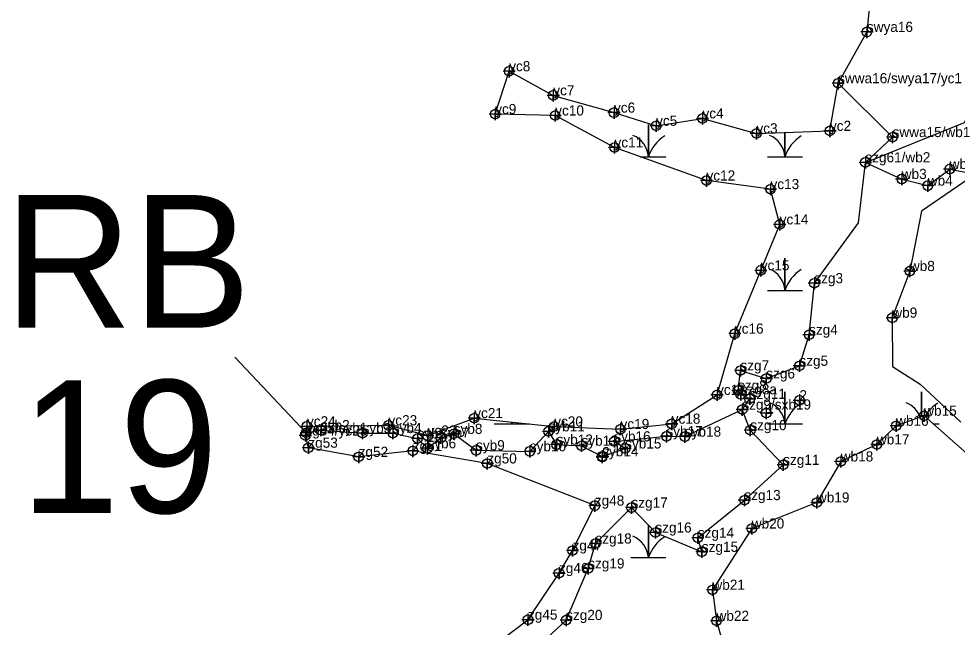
# Model space of a CAD drawing. Extents: x 2071991 to 2268989, y 436479 to 469629.
# Drawn here: x 2217530 to 2217991.7, y 438642 to 438941.5 of the extents above; entities that cross this region are included whole.
import ezdxf

# ---------------------------------------------------------------- set-up
doc = ezdxf.new("R2010")
doc.units = 0
for name, color, linetype in [('Default', 7, 'Continuous'), ('Exist Environmental Wetland Boundary', 7, 'Continuous'), ('Exist Environmental Wetland Boundary Cogo Comment', 7, 'Continuous'), ('Exist Environmental Wetland Boundary Cogo Point CELL', 7, 'Continuous'), ('Exist Hydro Jurisdictional Stream or Body of Water NEU Mitigable', 7, 'Continuous'), ('Exist Hydro Jurisdictional Stream or Body of Water NEU Mitigable Cogo Comment', 7, 'Continuous'), ('Exist Hydro Jurisdictional Stream or Body of Water NEU Mitigable Cogo Point CELL', 7, 'Continuous'), ('Exist Hydro Jurisdictional Stream or Body of Water NEU NonMitigable', 7, 'Continuous'), ('Exist Hydro Jurisdictional Stream or Body of Water NEU NonMitigable Cogo Comment', 7, 'Continuous'), ('Exist Hydro Jurisdictional Stream or Body of Water NEU NonMitigable Cogo Point CELL', 7, 'Continuous'), ('Exist Hydro Swamp or Marsh', 7, 'Continuous')]:
    doc.layers.add(name, color=color, linetype=linetype)

msp = doc.modelspace()

# ---------------------------------------------------------------- linework, layer by layer
at = {"layer": 'Default'}
msp.add_line((2217636.33, 438774.91), (2217671.41, 438737.63), dxfattribs=at)
at = {"layer": 'Exist Environmental Wetland Boundary'}
for points in [[(2217760.94, 438630.93), (2217780.52, 438645.68), (2217795.78, 438668.61), (2217802.43, 438679.75), (2217813.4, 438701.83), (2217760.51, 438722.59), (2217723.84, 438728.75), (2217697.22, 438725.8), (2217672.46, 438730.32), (2217671, 438736.35), (2217671.78, 438740.85), (2217711.9, 438741.36), (2217731.17, 438736.28), (2217754.08, 438744.89), (2217793.42, 438740.78), (2217826.06, 438739.52), (2217851.21, 438742.14), (2217873.53, 438756.36), (2217882.3, 438786.48), (2217895.04, 438817.63), (2217904.35, 438840.25), (2217899.83, 438857.62), (2217868.34, 438861.82), (2217823.08, 438878.14), (2217793.91, 438893.84), (2217764.38, 438894.56), (2217771.26, 438915.63), (2217792.96, 438903.78), (2217822.84, 438895.26), (2217843.55, 438888.8), (2217866.37, 438892.43), (2217892.9, 438885.05), (2217929.08, 438886.27), (2217933.09, 438909.73)], [(2217959.87, 438883.23), (2217946.5, 438870.8), (2217964.4, 438862.6), (2217977.21, 438859.33), (2217988, 438867.51), (2218000.66, 438865.02), (2217974.07, 438846.77), (2217968.39, 438817.3), (2217959.76, 438794.33), (2217959.88, 438770.28), (2217973.44, 438761.55), (2217993.4, 438742.94)], [(2217999.14, 438725.02), (2217975.44, 438746.08), (2217961.62, 438741.12), (2217952.17, 438731.95), (2217934.39, 438723.56), (2217922.67, 438703.38), (2217890.61, 438690.57), (2217871.26, 438660.41), (2217873.28, 438645.11), (2217881.02, 438617.93)]]:
    msp.add_lwpolyline(points, dxfattribs=at)
at = {"layer": 'Exist Environmental Wetland Boundary Cogo Point CELL'}
for points in [[(2217771.26, 438918.63), (2217771.26, 438912.63), (2217771.26, 438915.63), (2217774.26, 438915.63), (2217768.26, 438915.63)], [(2217792.96, 438906.78), (2217792.96, 438900.78), (2217792.96, 438903.78), (2217795.96, 438903.78), (2217789.96, 438903.78)], [(2217822.84, 438898.26), (2217822.84, 438892.26), (2217822.84, 438895.26), (2217825.84, 438895.26), (2217819.84, 438895.26)], [(2217764.38, 438897.56), (2217764.38, 438891.56), (2217764.38, 438894.56), (2217767.38, 438894.56), (2217761.38, 438894.56)], [(2217793.91, 438896.84), (2217793.91, 438890.84), (2217793.91, 438893.84), (2217796.91, 438893.84), (2217790.91, 438893.84)], [(2217866.37, 438895.43), (2217866.37, 438889.43), (2217866.37, 438892.43), (2217869.37, 438892.43), (2217863.37, 438892.43)], [(2217843.55, 438891.8), (2217843.55, 438885.8), (2217843.55, 438888.8), (2217846.55, 438888.8), (2217840.55, 438888.8)], [(2217929.08, 438889.27), (2217929.08, 438883.27), (2217929.08, 438886.27), (2217932.08, 438886.27), (2217926.08, 438886.27)], [(2217892.9, 438888.05), (2217892.9, 438882.05), (2217892.9, 438885.05), (2217895.9, 438885.05), (2217889.9, 438885.05)], [(2217823.08, 438881.14), (2217823.08, 438875.14), (2217823.08, 438878.14), (2217826.08, 438878.14), (2217820.08, 438878.14)], [(2217946.5, 438873.8), (2217946.5, 438867.8), (2217946.5, 438870.8), (2217949.5, 438870.8), (2217943.5, 438870.8)], [(2217988, 438870.51), (2217988, 438864.51), (2217988, 438867.51), (2217991, 438867.51), (2217985, 438867.51)], [(2217964.4, 438865.6), (2217964.4, 438859.6), (2217964.4, 438862.6), (2217967.4, 438862.6), (2217961.4, 438862.6)], [(2217868.34, 438864.82), (2217868.34, 438858.82), (2217868.34, 438861.82), (2217871.34, 438861.82), (2217865.34, 438861.82)], [(2217977.21, 438862.33), (2217977.21, 438856.33), (2217977.21, 438859.33), (2217980.21, 438859.33), (2217974.21, 438859.33)], [(2217899.83, 438860.62), (2217899.83, 438854.62), (2217899.83, 438857.62), (2217902.83, 438857.62), (2217896.83, 438857.62)], [(2217904.35, 438843.25), (2217904.35, 438837.25), (2217904.35, 438840.25), (2217907.35, 438840.25), (2217901.35, 438840.25)], [(2217895.04, 438820.63), (2217895.04, 438814.63), (2217895.04, 438817.63), (2217898.04, 438817.63), (2217892.04, 438817.63)], [(2217968.39, 438820.3), (2217968.39, 438814.3), (2217968.39, 438817.3), (2217971.39, 438817.3), (2217965.39, 438817.3)], [(2217959.76, 438797.33), (2217959.76, 438791.33), (2217959.76, 438794.33), (2217962.76, 438794.33), (2217956.76, 438794.33)], [(2217882.3, 438789.48), (2217882.3, 438783.48), (2217882.3, 438786.48), (2217885.3, 438786.48), (2217879.3, 438786.48)], [(2217873.53, 438759.36), (2217873.53, 438753.36), (2217873.53, 438756.36), (2217876.53, 438756.36), (2217870.53, 438756.36)], [(2217754.08, 438747.89), (2217754.08, 438741.89), (2217754.08, 438744.89), (2217757.08, 438744.89), (2217751.08, 438744.89)], [(2217975.44, 438749.08), (2217975.44, 438743.08), (2217975.44, 438746.08), (2217978.44, 438746.08), (2217972.44, 438746.08)], [(2217671.78, 438743.85), (2217671.78, 438737.85), (2217671.78, 438740.85), (2217674.78, 438740.85), (2217668.78, 438740.85)], [(2217711.9, 438744.36), (2217711.9, 438738.36), (2217711.9, 438741.36), (2217714.9, 438741.36), (2217708.9, 438741.36)], [(2217793.42, 438743.78), (2217793.42, 438737.78), (2217793.42, 438740.78), (2217796.42, 438740.78), (2217790.42, 438740.78)], [(2217826.06, 438742.52), (2217826.06, 438736.52), (2217826.06, 438739.52), (2217829.06, 438739.52), (2217823.06, 438739.52)], [(2217851.21, 438745.14), (2217851.21, 438739.14), (2217851.21, 438742.14), (2217854.21, 438742.14), (2217848.21, 438742.14)], [(2217961.62, 438744.12), (2217961.62, 438738.12), (2217961.62, 438741.12), (2217964.62, 438741.12), (2217958.62, 438741.12)], [(2217671, 438739.35), (2217671, 438733.35), (2217671, 438736.35), (2217674, 438736.35), (2217668, 438736.35)], [(2217731.17, 438739.28), (2217731.17, 438733.28), (2217731.17, 438736.28), (2217734.17, 438736.28), (2217728.17, 438736.28)], [(2217672.46, 438733.32), (2217672.46, 438727.32), (2217672.46, 438730.32), (2217675.46, 438730.32), (2217669.46, 438730.32)], [(2217723.84, 438731.75), (2217723.84, 438725.75), (2217723.84, 438728.75), (2217726.84, 438728.75), (2217720.84, 438728.75)], [(2217952.17, 438734.95), (2217952.17, 438728.95), (2217952.17, 438731.95), (2217955.17, 438731.95), (2217949.17, 438731.95)], [(2217697.22, 438728.8), (2217697.22, 438722.8), (2217697.22, 438725.8), (2217700.22, 438725.8), (2217694.22, 438725.8)], [(2217760.51, 438725.59), (2217760.51, 438719.59), (2217760.51, 438722.59), (2217763.51, 438722.59), (2217757.51, 438722.59)], [(2217934.39, 438726.56), (2217934.39, 438720.56), (2217934.39, 438723.56), (2217937.39, 438723.56), (2217931.39, 438723.56)], [(2217813.4, 438704.83), (2217813.4, 438698.83), (2217813.4, 438701.83), (2217816.4, 438701.83), (2217810.4, 438701.83)], [(2217922.67, 438706.38), (2217922.67, 438700.38), (2217922.67, 438703.38), (2217925.67, 438703.38), (2217919.67, 438703.38)], [(2217890.61, 438693.57), (2217890.61, 438687.57), (2217890.61, 438690.57), (2217893.61, 438690.57), (2217887.61, 438690.57)], [(2217802.43, 438682.75), (2217802.43, 438676.75), (2217802.43, 438679.75), (2217805.43, 438679.75), (2217799.43, 438679.75)], [(2217795.78, 438671.61), (2217795.78, 438665.61), (2217795.78, 438668.61), (2217798.78, 438668.61), (2217792.78, 438668.61)], [(2217871.26, 438663.41), (2217871.26, 438657.41), (2217871.26, 438660.41), (2217874.26, 438660.41), (2217868.26, 438660.41)], [(2217780.52, 438648.68), (2217780.52, 438642.68), (2217780.52, 438645.68), (2217783.52, 438645.68), (2217777.52, 438645.68)], [(2217873.28, 438648.11), (2217873.28, 438642.11), (2217873.28, 438645.11), (2217876.28, 438645.11), (2217870.28, 438645.11)]]:
    msp.add_lwpolyline(points, dxfattribs=at)
for centre in [(2217771.26, 438915.63), (2217792.96, 438903.78), (2217764.38, 438894.56), (2217793.91, 438893.84), (2217822.84, 438895.26), (2217866.37, 438892.43), (2217843.55, 438888.8), (2217892.9, 438885.05), (2217929.08, 438886.27), (2217823.08, 438878.14), (2217946.5, 438870.8), (2217988, 438867.51), (2217868.34, 438861.82), (2217964.4, 438862.6), (2217977.21, 438859.33), (2217899.83, 438857.62), (2217904.35, 438840.25), (2217895.04, 438817.63), (2217968.39, 438817.3), (2217959.76, 438794.33), (2217882.3, 438786.48), (2217873.53, 438756.36), (2217754.08, 438744.89), (2217975.44, 438746.08), (2217671.78, 438740.85), (2217711.9, 438741.36), (2217793.42, 438740.78), (2217826.06, 438739.52), (2217851.21, 438742.14), (2217961.62, 438741.12), (2217671, 438736.35), (2217731.17, 438736.28), (2217672.46, 438730.32), (2217952.17, 438731.95), (2217697.22, 438725.8), (2217723.84, 438728.75), (2217760.51, 438722.59), (2217934.39, 438723.56), (2217813.4, 438701.83), (2217922.67, 438703.38), (2217890.61, 438690.57), (2217802.43, 438679.75), (2217795.78, 438668.61), (2217871.26, 438660.41), (2217780.52, 438645.68), (2217873.28, 438645.11)]:
    msp.add_circle(centre, 2.34, dxfattribs=at)
at = {"layer": 'Exist Hydro Jurisdictional Stream or Body of Water NEU Mitigable'}
for points in [[(2217789.94, 438636.76), (2217799.31, 438645.52), (2217810.15, 438670.89), (2217813.7, 438683.16), (2217831.43, 438700.84), (2217843.19, 438688.59), (2217866.04, 438679.08), (2217864.06, 438685.99), (2217886.98, 438704.54), (2217906.08, 438721.89), (2217889.9, 438738.97), (2217885.95, 438749.1), (2217889.58, 438754.39), (2217885.17, 438756.6), (2217883.84, 438758.54), (2217885.04, 438768.35), (2217897.76, 438764.41), (2217914.05, 438770.65), (2217918.81, 438785.95), (2217921.39, 438811.3), (2217943.04, 438840.96), (2217946.5, 438870.8)], [(2217671.41, 438737.63), (2217678.68, 438738.96), (2217699.14, 438737.49), (2217714.03, 438737.53), (2217726.13, 438734.84), (2217731.05, 438730.04), (2217737.7, 438735.26), (2217743.98, 438737.16), (2217754.98, 438729.06), (2217781.43, 438728.55), (2217790.62, 438738.38), (2217794.6, 438731.84), (2217806.86, 438731.31), (2217817.02, 438726.09), (2217828.32, 438729.95), (2217823.01, 438733.44), (2217848.63, 438735.95), (2217857.69, 438735.78), (2217885.95, 438749.1)]]:
    msp.add_lwpolyline(points, dxfattribs=at)
at = {"layer": 'Exist Hydro Jurisdictional Stream or Body of Water NEU Mitigable Cogo Point CELL'}
for points in [[(2217921.39, 438814.3), (2217921.39, 438808.3), (2217921.39, 438811.3), (2217924.39, 438811.3), (2217918.39, 438811.3)], [(2217918.81, 438788.95), (2217918.81, 438782.95), (2217918.81, 438785.95), (2217921.81, 438785.95), (2217915.81, 438785.95)], [(2217914.05, 438773.65), (2217914.05, 438767.65), (2217914.05, 438770.65), (2217917.05, 438770.65), (2217911.05, 438770.65)], [(2217885.04, 438771.35), (2217885.04, 438765.35), (2217885.04, 438768.35), (2217888.04, 438768.35), (2217882.04, 438768.35)], [(2217897.76, 438767.41), (2217897.76, 438761.41), (2217897.76, 438764.41), (2217900.76, 438764.41), (2217894.76, 438764.41)], [(2217883.84, 438761.54), (2217883.84, 438755.54), (2217883.84, 438758.54), (2217886.84, 438758.54), (2217880.84, 438758.54)], [(2217885.17, 438759.6), (2217885.17, 438753.6), (2217885.17, 438756.6), (2217888.17, 438756.6), (2217882.17, 438756.6)], [(2217889.58, 438757.39), (2217889.58, 438751.39), (2217889.58, 438754.39), (2217892.58, 438754.39), (2217886.58, 438754.39)], [(2217914.05, 438756.65), (2217914.05, 438750.65), (2217914.05, 438753.65), (2217917.05, 438753.65), (2217911.05, 438753.65)], [(2217885.95, 438752.1), (2217885.95, 438746.1), (2217885.95, 438749.1), (2217888.95, 438749.1), (2217882.95, 438749.1)], [(2217897.76, 438750.41), (2217897.76, 438744.41), (2217897.76, 438747.41), (2217900.76, 438747.41), (2217894.76, 438747.41)], [(2217678.68, 438741.96), (2217678.68, 438735.96), (2217678.68, 438738.96), (2217681.68, 438738.96), (2217675.68, 438738.96)], [(2217790.62, 438741.38), (2217790.62, 438735.38), (2217790.62, 438738.38), (2217793.62, 438738.38), (2217787.62, 438738.38)], [(2217889.9, 438741.97), (2217889.9, 438735.97), (2217889.9, 438738.97), (2217892.9, 438738.97), (2217886.9, 438738.97)], [(2217671.41, 438740.63), (2217671.41, 438734.63), (2217671.41, 438737.63), (2217674.41, 438737.63), (2217668.41, 438737.63)], [(2217699.14, 438740.49), (2217699.14, 438734.49), (2217699.14, 438737.49), (2217702.14, 438737.49), (2217696.14, 438737.49)], [(2217714.03, 438740.53), (2217714.03, 438734.53), (2217714.03, 438737.53), (2217717.03, 438737.53), (2217711.03, 438737.53)], [(2217726.13, 438737.84), (2217726.13, 438731.84), (2217726.13, 438734.84), (2217729.13, 438734.84), (2217723.13, 438734.84)], [(2217737.7, 438738.26), (2217737.7, 438732.26), (2217737.7, 438735.26), (2217740.7, 438735.26), (2217734.7, 438735.26)], [(2217743.98, 438740.16), (2217743.98, 438734.16), (2217743.98, 438737.16), (2217746.98, 438737.16), (2217740.98, 438737.16)], [(2217823.01, 438736.44), (2217823.01, 438730.44), (2217823.01, 438733.44), (2217826.01, 438733.44), (2217820.01, 438733.44)], [(2217848.63, 438738.95), (2217848.63, 438732.95), (2217848.63, 438735.95), (2217851.63, 438735.95), (2217845.63, 438735.95)], [(2217857.69, 438738.78), (2217857.69, 438732.78), (2217857.69, 438735.78), (2217860.69, 438735.78), (2217854.69, 438735.78)], [(2217731.05, 438733.04), (2217731.05, 438727.04), (2217731.05, 438730.04), (2217734.05, 438730.04), (2217728.05, 438730.04)], [(2217754.98, 438732.06), (2217754.98, 438726.06), (2217754.98, 438729.06), (2217757.98, 438729.06), (2217751.98, 438729.06)], [(2217794.6, 438734.84), (2217794.6, 438728.84), (2217794.6, 438731.84), (2217797.6, 438731.84), (2217791.6, 438731.84)], [(2217806.86, 438734.31), (2217806.86, 438728.31), (2217806.86, 438731.31), (2217809.86, 438731.31), (2217803.86, 438731.31)], [(2217828.32, 438732.95), (2217828.32, 438726.95), (2217828.32, 438729.95), (2217831.32, 438729.95), (2217825.32, 438729.95)], [(2217781.43, 438731.55), (2217781.43, 438725.55), (2217781.43, 438728.55), (2217784.43, 438728.55), (2217778.43, 438728.55)], [(2217817.02, 438729.09), (2217817.02, 438723.09), (2217817.02, 438726.09), (2217820.02, 438726.09), (2217814.02, 438726.09)], [(2217817.02, 438728.71), (2217817.02, 438722.71), (2217817.02, 438725.71), (2217820.02, 438725.71), (2217814.02, 438725.71)], [(2217906.08, 438724.89), (2217906.08, 438718.89), (2217906.08, 438721.89), (2217909.08, 438721.89), (2217903.08, 438721.89)], [(2217886.98, 438707.54), (2217886.98, 438701.54), (2217886.98, 438704.54), (2217889.98, 438704.54), (2217883.98, 438704.54)], [(2217831.43, 438703.84), (2217831.43, 438697.84), (2217831.43, 438700.84), (2217834.43, 438700.84), (2217828.43, 438700.84)], [(2217843.19, 438691.59), (2217843.19, 438685.59), (2217843.19, 438688.59), (2217846.19, 438688.59), (2217840.19, 438688.59)], [(2217813.7, 438686.16), (2217813.7, 438680.16), (2217813.7, 438683.16), (2217816.7, 438683.16), (2217810.7, 438683.16)], [(2217864.06, 438688.99), (2217864.06, 438682.99), (2217864.06, 438685.99), (2217867.06, 438685.99), (2217861.06, 438685.99)], [(2217866.04, 438682.08), (2217866.04, 438676.08), (2217866.04, 438679.08), (2217869.04, 438679.08), (2217863.04, 438679.08)], [(2217810.15, 438673.89), (2217810.15, 438667.89), (2217810.15, 438670.89), (2217813.15, 438670.89), (2217807.15, 438670.89)], [(2217799.31, 438648.52), (2217799.31, 438642.52), (2217799.31, 438645.52), (2217802.31, 438645.52), (2217796.31, 438645.52)]]:
    msp.add_lwpolyline(points, dxfattribs=at)
for centre in [(2217921.39, 438811.3), (2217918.81, 438785.95), (2217885.04, 438768.35), (2217914.05, 438770.65), (2217897.76, 438764.41), (2217883.84, 438758.54), (2217885.17, 438756.6), (2217889.58, 438754.39), (2217914.05, 438753.65), (2217885.95, 438749.1), (2217897.76, 438747.41), (2217678.68, 438738.96), (2217889.9, 438738.97), (2217671.41, 438737.63), (2217699.14, 438737.49), (2217714.03, 438737.53), (2217726.13, 438734.84), (2217737.7, 438735.26), (2217743.98, 438737.16), (2217790.62, 438738.38), (2217848.63, 438735.95), (2217857.69, 438735.78), (2217731.05, 438730.04), (2217794.6, 438731.84), (2217806.86, 438731.31), (2217823.01, 438733.44), (2217828.32, 438729.95), (2217754.98, 438729.06), (2217781.43, 438728.55), (2217817.02, 438726.09), (2217817.02, 438725.71), (2217906.08, 438721.89), (2217886.98, 438704.54), (2217831.43, 438700.84), (2217843.19, 438688.59), (2217813.7, 438683.16), (2217864.06, 438685.99), (2217866.04, 438679.08), (2217810.15, 438670.89), (2217799.31, 438645.52)]:
    msp.add_circle(centre, 2.34, dxfattribs=at)
at = {"layer": 'Exist Hydro Jurisdictional Stream or Body of Water NEU NonMitigable'}
msp.add_lwpolyline([(2217951.55, 438977.67), (2217947.25, 438934.98), (2217933.09, 438909.73), (2217959.87, 438883.23), (2217946.5, 438870.8), (2217995.23, 438890.36), (2218006.61, 438908.97), (2218012.02, 438933.04), (2218026.19, 438966.68)], dxfattribs=at)
at = {"layer": 'Exist Hydro Jurisdictional Stream or Body of Water NEU NonMitigable Cogo Point CELL'}
for points in [[(2217947.25, 438937.98), (2217947.25, 438931.98), (2217947.25, 438934.98), (2217950.25, 438934.98), (2217944.25, 438934.98)], [(2217933.09, 438912.73), (2217933.09, 438906.73), (2217933.09, 438909.73), (2217936.09, 438909.73), (2217930.09, 438909.73)], [(2217959.87, 438886.23), (2217959.87, 438880.23), (2217959.87, 438883.23), (2217962.87, 438883.23), (2217956.87, 438883.23)]]:
    msp.add_lwpolyline(points, dxfattribs=at)
for centre in [(2217947.25, 438934.98), (2217933.09, 438909.73), (2217959.87, 438883.23)]:
    msp.add_circle(centre, 2.34, dxfattribs=at)
at = {"layer": 'Exist Hydro Swamp or Marsh'}
msp.add_line((2217980.01, 438742.02), (2217982.74, 438742.02), dxfattribs=at)
for points in [[(2217835.71, 438873.59), (2217839.74, 438873.59), (2217839.74, 438889.37), (2217839.74, 438873.59), (2217848.34, 438873.59)], [(2217898.34, 438873.59), (2217906.94, 438873.59), (2217906.94, 438885.53)], [(2217906.94, 438885.53), (2217906.94, 438873.59), (2217915.54, 438873.59)], [(2217898.34, 438807.8), (2217906.94, 438807.8), (2217906.94, 438823.59), (2217906.94, 438807.8), (2217915.54, 438807.8)], [(2217898.34, 438742.02), (2217906.94, 438742.02), (2217906.94, 438757.8), (2217906.94, 438742.02), (2217915.54, 438742.02)], [(2217974.14, 438745.62), (2217974.14, 438757.8), (2217974.14, 438745.62)], [(2217763.93, 438742.02), (2217772.53, 438742.02), (2217772.53, 438742.96)], [(2217772.53, 438742.96), (2217772.53, 438742.02), (2217781.13, 438742.02)], [(2217831.13, 438676.24), (2217839.74, 438676.24), (2217839.74, 438692.02), (2217839.74, 438676.24), (2217848.34, 438676.24)]]:
    msp.add_lwpolyline(points, dxfattribs=at)
for centre, radius, start, end in [((2217827.47, 438872.7), 12.3, 4.1403, 67.535), ((2217894.67, 438872.7), 12.3, 4.1403, 67.535), ((2217857.98, 438867.52), 19.22, 122.1274, 161.6222), ((2217925.18, 438867.52), 19.22, 122.1274, 161.6222), ((2217894.67, 438806.92), 12.3, 4.1403, 67.535), ((2217925.18, 438801.74), 19.22, 122.1274, 161.6222), ((2217961.88, 438806.92), 12.3, 57.9471, 67.535), ((2217894.67, 438741.14), 12.3, 4.1403, 67.535), ((2217925.18, 438735.96), 19.22, 122.1274, 161.6222), ((2217961.88, 438741.14), 12.3, 20.0793, 67.535), ((2217992.38, 438735.96), 19.22, 122.1274, 149.4358), ((2217760.27, 438741.14), 12.3, 4.1403, 8.5979), ((2217790.77, 438735.96), 19.22, 158.7532, 161.6222), ((2217827.47, 438675.36), 12.3, 4.1403, 67.535), ((2217857.98, 438670.18), 19.22, 122.1274, 161.6222)]:
    msp.add_arc(centre, radius, start, end, dxfattribs=at)

# ---------------------------------------------------------------- texts
at = {"layer": 'Default'}
for s, p in [('RB', (2217522.83, 438789.38)), ('19', (2217530.88, 438698.24))]:
    msp.add_text(s, height=65.34, dxfattribs=at).set_placement(p)
at = {"layer": 'Exist Environmental Wetland Boundary Cogo Comment'}
for s, p in [('yc8', (2217771.26, 438915.63)), ('yc7', (2217792.96, 438903.78)), ('yc9', (2217764.38, 438894.56)), ('yc10', (2217793.91, 438893.84)), ('yc6', (2217822.84, 438895.26)), ('yc5', (2217843.55, 438888.8)), ('yc4', (2217866.37, 438892.43)), ('yc3', (2217892.9, 438885.05)), ('yc2', (2217929.08, 438886.27)), ('yc11', (2217823.08, 438878.14)), ('wb5', (2217988, 438867.51)), ('yc12', (2217868.34, 438861.82)), ('wb3', (2217964.4, 438862.6)), ('yc13', (2217899.83, 438857.62)), ('wb4', (2217977.21, 438859.33)), ('yc14', (2217904.35, 438840.25)), ('yc15', (2217895.04, 438817.63)), ('wb8', (2217968.39, 438817.3)), ('wb9', (2217959.76, 438794.33)), ('yc16', (2217882.3, 438786.48)), ('yc17', (2217873.53, 438756.36)), ('wb15', (2217975.44, 438746.08)), ('yc24', (2217671.78, 438740.85)), ('yc23', (2217711.9, 438741.36)), ('yc21', (2217754.08, 438744.89)), ('yc20', (2217793.42, 438740.78)), ('yc18', (2217851.21, 438742.14)), ('wb16', (2217961.62, 438741.12)), ('zg54/yc25', (2217671, 438736.35)), ('yc19', (2217826.06, 438739.52)), ('wb17', (2217952.17, 438731.95)), ('zg53', (2217672.46, 438730.32)), ('zg51', (2217723.84, 438728.75)), ('zg52', (2217697.22, 438725.8)), ('zg50', (2217760.51, 438722.59)), ('wb18', (2217934.39, 438723.56)), ('wb19', (2217922.67, 438703.38)), ('zg48', (2217813.4, 438701.83)), ('wb20', (2217890.61, 438690.57)), ('zg47', (2217802.43, 438679.75)), ('zg46', (2217795.78, 438668.61)), ('wb21', (2217871.26, 438660.41)), ('zg45', (2217780.52, 438645.68)), ('wb22', (2217873.28, 438645.11))]:
    msp.add_text(s, height=5, dxfattribs=at).set_placement(p)
at = {"layer": 'Exist Hydro Jurisdictional Stream or Body of Water NEU Mitigable Cogo Comment'}
for s, p in [('szg61/wb2', (2217946.5, 438870.8)), ('szg3', (2217921.39, 438811.3)), ('szg4', (2217918.81, 438785.95)), ('szg7', (2217885.04, 438768.35)), ('szg5', (2217914.05, 438770.65)), ('szg6', (2217897.76, 438764.41)), ('szg8', (2217883.84, 438758.54)), ('szg8a', (2217885.17, 438756.6)), ('szg11', (2217889.58, 438754.39)), ('2', (2217914.05, 438753.65)), ('szg9/sxb19', (2217885.95, 438749.1)), ('1', (2217897.76, 438747.41)), ('yc25/syb1', (2217671.41, 438737.63)), ('syb2', (2217678.68, 438738.96)), ('syb3', (2217699.14, 438737.49)), ('syb4', (2217714.03, 438737.53)), ('yc22', (2217731.17, 438736.28)), ('syb8', (2217743.98, 438737.16)), ('syb11', (2217790.62, 438738.38)), ('syb17', (2217848.63, 438735.95)), ('syb18', (2217857.69, 438735.78)), ('szg10', (2217889.9, 438738.97)), ('syb5', (2217726.13, 438734.84)), ('syb7', (2217737.7, 438735.26)), ('syb12', (2217794.6, 438731.84)), ('syb13', (2217806.86, 438731.31)), ('syb16', (2217823.01, 438733.44)), ('syb6', (2217731.05, 438730.04)), ('syb9', (2217754.98, 438729.06)), ('syb10', (2217781.43, 438728.55)), ('syb15', (2217828.32, 438729.95)), ('syb14', (2217817.02, 438726.09)), ('2', (2217817.02, 438725.71)), ('szg11', (2217906.08, 438721.89)), ('szg13', (2217886.98, 438704.54)), ('szg17', (2217831.43, 438700.84)), ('szg16', (2217843.19, 438688.59)), ('szg14', (2217864.06, 438685.99)), ('szg18', (2217813.7, 438683.16)), ('szg15', (2217866.04, 438679.08)), ('szg19', (2217810.15, 438670.89)), ('szg20', (2217799.31, 438645.52))]:
    msp.add_text(s, height=5, dxfattribs=at).set_placement(p)
at = {"layer": 'Exist Hydro Jurisdictional Stream or Body of Water NEU NonMitigable Cogo Comment'}
for s, p in [('swya16', (2217947.25, 438934.98)), ('swwa16/swya17/yc1', (2217933.09, 438909.73)), ('swwa15/wb1', (2217959.87, 438883.23))]:
    msp.add_text(s, height=5, dxfattribs=at).set_placement(p)

doc.saveas('drawing.dxf')
